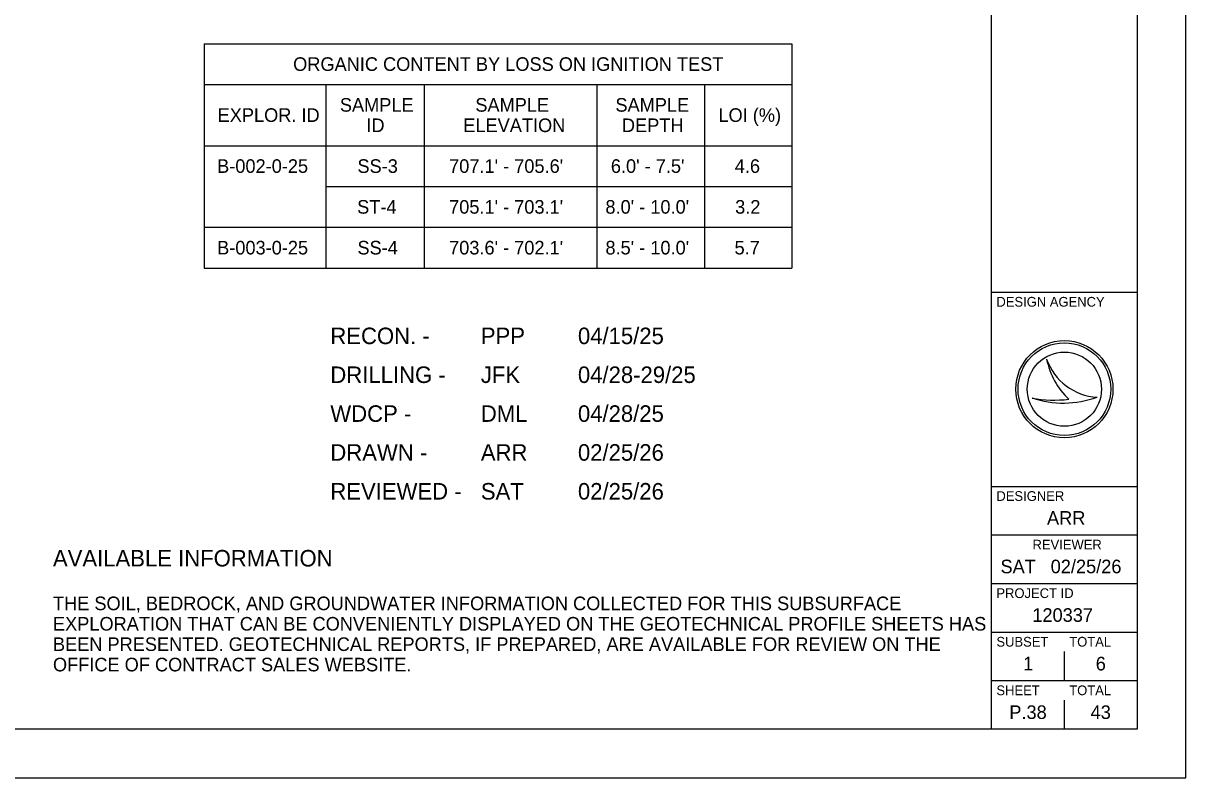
# Model space of a CAD drawing. Extents: x 0 to 34, y 0 to 22.
# Drawn here: x 22.03 to 34, y 0 to 7.77 of the extents above; entities that cross this region are included whole.
import ezdxf

# ---------------------------------------------------------------- set-up
doc = ezdxf.new("R2010")
doc.units = 0
for name, color, linetype in [('SH_Border', 7, 'Continuous'), ('SH_Cut_Line', 7, 'Continuous'), ('SH_Data', 7, 'Continuous'), ('SH_Text', 7, 'Continuous')]:
    doc.layers.add(name, color=color, linetype=linetype)

msp = doc.modelspace()

# ---------------------------------------------------------------- linework, layer by layer
at = {"layer": 'SH_Border'}
for p, q in [((32, 0.5), (32, 21.5)), ((32, 5), (33.5, 5)), ((32, 3), (33.5, 3)), ((32, 2.5), (33.5, 2.5)), ((32, 2), (33.5, 2)), ((32, 1.5), (33.5, 1.5)), ((32, 1), (33.5, 1))]:
    msp.add_line(p, q, dxfattribs=at)
msp.add_lwpolyline([(1.5, 21.5), (33.5, 21.5), (33.5, 0.5), (1.5, 0.5)], close=True, dxfattribs=at)
at = {"layer": 'SH_Cut_Line'}
msp.add_lwpolyline([(0, 0), (34, 0), (34, 22), (0, 22)], close=True, dxfattribs=at)
at = {"layer": 'SH_Data'}
for p, q in [((23.889, 7.557), (23.889, 5.247)), ((23.889, 7.557), (29.944, 7.557)), ((29.944, 7.557), (29.944, 5.247)), ((23.889, 7.137), (29.944, 7.137)), ((25.148, 5.247), (25.148, 7.137)), ((26.161, 5.247), (26.161, 7.137)), ((27.939, 5.247), (27.939, 7.137)), ((29.047, 5.247), (29.047, 7.137)), ((23.889, 6.507), (29.944, 6.507)), ((25.148, 6.087), (29.944, 6.087)), ((23.889, 5.667), (29.944, 5.667)), ((23.889, 5.247), (29.944, 5.247)), ((32.567, 4.31), (32.567, 4.31)), ((32.75, 4), (32.75, 4)), ((32.417, 3.91), (32.417, 3.91)), ((33.087, 3.919), (33.087, 3.919)), ((32.75, 1), (32.75, 1.3)), ((32.75, 0.5), (32.75, 0.8)), ((32.375, 0.675), (32.375, 0.675))]:
    msp.add_line(p, q, dxfattribs=at)
for radius in [0.5, 0.477, 0.477, 0.382]:
    msp.add_circle((32.75, 4), radius, dxfattribs=at)
for centre, radius, start, end in [((33.116, 4.498), 0.58, 198.9257, 198.9319), ((33.347, 4.47), 0.796, 191.6379, 191.6421), ((33.116, 4.498), 0.58, 198.9319, 267.1657), ((33.347, 4.47), 0.796, 191.6421, 226.0947), ((32.739, 4.87), 1.013, 251.4576, 290.0832), ((32.648, 5.154), 1.266, 259.4964, 259.4995), ((32.739, 4.87), 1.013, 251.4527, 251.4576), ((32.648, 5.154), 1.266, 259.4995, 276.6672)]:
    msp.add_arc(centre, radius, start, end, dxfattribs=at)

# ---------------------------------------------------------------- texts
for s, height, p in [('DESIGN AGENCY', 0.1, (32.05, 4.85)), ('DESIGNER', 0.1, (32.05, 2.85)), ('ARR', 0.14, (32.571, 2.605)), ('REVIEWER', 0.1, (32.422, 2.35)), ('SAT', 0.14, (32.092, 2.105)), ('02/25/26', 0.14, (32.609, 2.105)), ('PROJECT ID', 0.1, (32.05, 1.85)), ('120337', 0.14, (32.42, 1.605)), ('SUBSET', 0.1, (32.05, 1.35)), ('TOTAL', 0.1, (32.8, 1.35)), ('1', 0.14, (32.325, 1.105)), ('6', 0.14, (33.073, 1.105)), ('SHEET', 0.1, (32.05, 0.85)), ('TOTAL', 0.1, (32.8, 0.85)), ('P.38', 0.14, (32.183, 0.605)), ('43', 0.14, (33.02, 0.605))]:
    msp.add_text(s, height=height, dxfattribs=at).set_placement(p)
at = {"layer": 'SH_Text'}
for s, height, p in [('ORGANIC CONTENT BY LOSS ON IGNITION TEST', 0.14, (24.807, 7.277)), ('SAMPLE', 0.14, (25.288, 6.857)), ('SAMPLE', 0.14, (26.683, 6.857)), ('SAMPLE', 0.14, (28.126, 6.857)), ('EXPLOR. ID', 0.14, (24.029, 6.752)), ('LOI (%)', 0.14, (29.187, 6.752)), ('ID', 0.14, (25.561, 6.647)), ('ELEVATION', 0.14, (26.559, 6.647)), ('DEPTH', 0.14, (28.193, 6.647)), ('B-002-0-25', 0.14, (24.024, 6.227)), ('SS-3', 0.14, (25.469, 6.227)), ("707.1' - 705.6'", 0.14, (26.413, 6.227)), ("6.0' - 7.5'", 0.14, (28.079, 6.227)), ('4.6', 0.14, (29.355, 6.227)), ('ST-4', 0.14, (25.466, 5.807)), ("705.1' - 703.1'", 0.14, (26.413, 5.807)), ("8.0' - 10.0'", 0.14, (28.023, 5.807)), ('3.2', 0.14, (29.359, 5.807)), ('B-003-0-25', 0.14, (24.024, 5.387)), ('SS-4', 0.14, (25.469, 5.387)), ("703.6' - 702.1'", 0.14, (26.413, 5.387)), ("8.5' - 10.0'", 0.14, (28.023, 5.387)), ('5.7', 0.14, (29.353, 5.387)), ('RECON. -', 0.17, (25.19, 4.464)), ('PPP', 0.17, (26.74, 4.464)), ('04/15/25', 0.17, (27.74, 4.464)), ('DRILLING -', 0.17, (25.19, 4.064)), ('JFK', 0.17, (26.74, 4.064)), ('04/28-29/25', 0.17, (27.74, 4.064)), ('WDCP -', 0.17, (25.19, 3.664)), ('DML', 0.17, (26.74, 3.664)), ('04/28/25', 0.17, (27.74, 3.664)), ('DRAWN -', 0.17, (25.19, 3.264)), ('ARR', 0.17, (26.74, 3.264)), ('02/25/26', 0.17, (27.74, 3.264)), ('REVIEWED -', 0.17, (25.19, 2.864)), ('SAT', 0.17, (26.74, 2.864)), ('02/25/26', 0.17, (27.74, 2.864)), ('AVAILABLE INFORMATION', 0.17, (22.333, 2.175)), ('THE SOIL, BEDROCK, AND GROUNDWATER INFORMATION COLLECTED FOR THIS SUBSURFACE ', 0.14, (22.333, 1.725)), ('EXPLORATION THAT CAN BE CONVENIENTLY DISPLAYED ON THE GEOTECHNICAL PROFILE SHEETS HAS ', 0.14, (22.333, 1.515)), ('BEEN PRESENTED. GEOTECHNICAL REPORTS, IF PREPARED, ARE AVAILABLE FOR REVIEW ON THE ', 0.14, (22.333, 1.305)), ('OFFICE OF CONTRACT SALES WEBSITE.', 0.14, (22.333, 1.095))]:
    msp.add_text(s, height=height, dxfattribs=at).set_placement(p)

doc.saveas('drawing.dxf')
